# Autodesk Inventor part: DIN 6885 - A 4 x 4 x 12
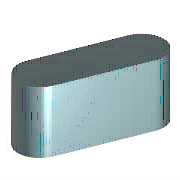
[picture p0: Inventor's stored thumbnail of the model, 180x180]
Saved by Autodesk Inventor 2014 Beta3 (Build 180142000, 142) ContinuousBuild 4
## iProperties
IsCustomPart: 0
Created: 2010-11
Part Number: DIN 6885 - A 4 x 4 x 12
Material: Steel, Mild
Description: Parallel Key
Document SubType Name: Modeling
Standard: DIN 6885
Designer: Beta-8540w
Standards Organization: DIN
Language: en-US
Size Designation: A 4 x 4 x 12
Categories: <MemberInstance><Categories><Category DisplayName="Shaft Parts" InternalName="7f7aeb1f-a693-4053-b835-cee3144e0d98" Mnemonic="SHFT"><Category DisplayName="Keys"
Density: 1 g/cm^3
Appearance: Steel
Author: Beta-8540w
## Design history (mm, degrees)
sketch "Sketch1"
  geometry: L1 (2, 2)-(10, 2); L2 (10, -2)-(2, -2); L3 (0, 9.4)-(0, -7.4) reference; L4 (-5, 0)-(30, 0) reference; L5 (12, 0)-(12, 7); A1 r 2 centre (2, 0) between (2, 2) and (2, -2); A2 r 2 centre (10, 0) between (10, -2) and (10, 2)
  constraints: 6 end point, 5 point on circle, 4 tangent, 3 point on line, 2 centre point, 1 horizontal, 1 parallel, 1 perpendicular
  dimensions: "d0" = 2 radius of A1 (= 0.5 x PB); "d8" = 2 radius of A2 (= 0.5 x PB); "d9" = 12 distance between parallel lines of L5 L3 (= NLG)
extrude "Body1" new body sketch "Sketch1" taper "d3" = 0 deg; stored distance "d4" = 10
workplane "Work Plane3"
body "Solid1"
workplane "Work Plane1"
workplane "Work Plane2"
other parameters: "d1" = -2.5 (= -PNT), "d2" = 1.5 (= PH - PNT), "NLG" = 12 [user parameter; used in 3 equation terms], "PB" = 4 [user parameter; used in 2 equation terms], "PNT" = 2.5 [user parameter; used in 2 equation terms], "PH" = 4 [user parameter; used in 1 equation term], "d7" = 0, "d15" = 0, "d16" = 0, "d17" = 0, "RR" = 0.001 [user parameter], "PHH" = 0 [user parameter], "WDMAX" = 12 [user parameter], "PLB1" = 12 (= NLG) [user parameter], "PLB2" = 12 (= NLG) [user parameter], "PUEB" = 1.8 [user parameter]
